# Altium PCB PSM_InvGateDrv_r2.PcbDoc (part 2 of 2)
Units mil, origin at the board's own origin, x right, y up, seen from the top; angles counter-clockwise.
Board outline 5413.39 x 2000 mil, 2 copper layers (Top Layer, Bottom Layer), stack 62 mil thick; 132 components, 58 nets, 317 pads, 172 vias.
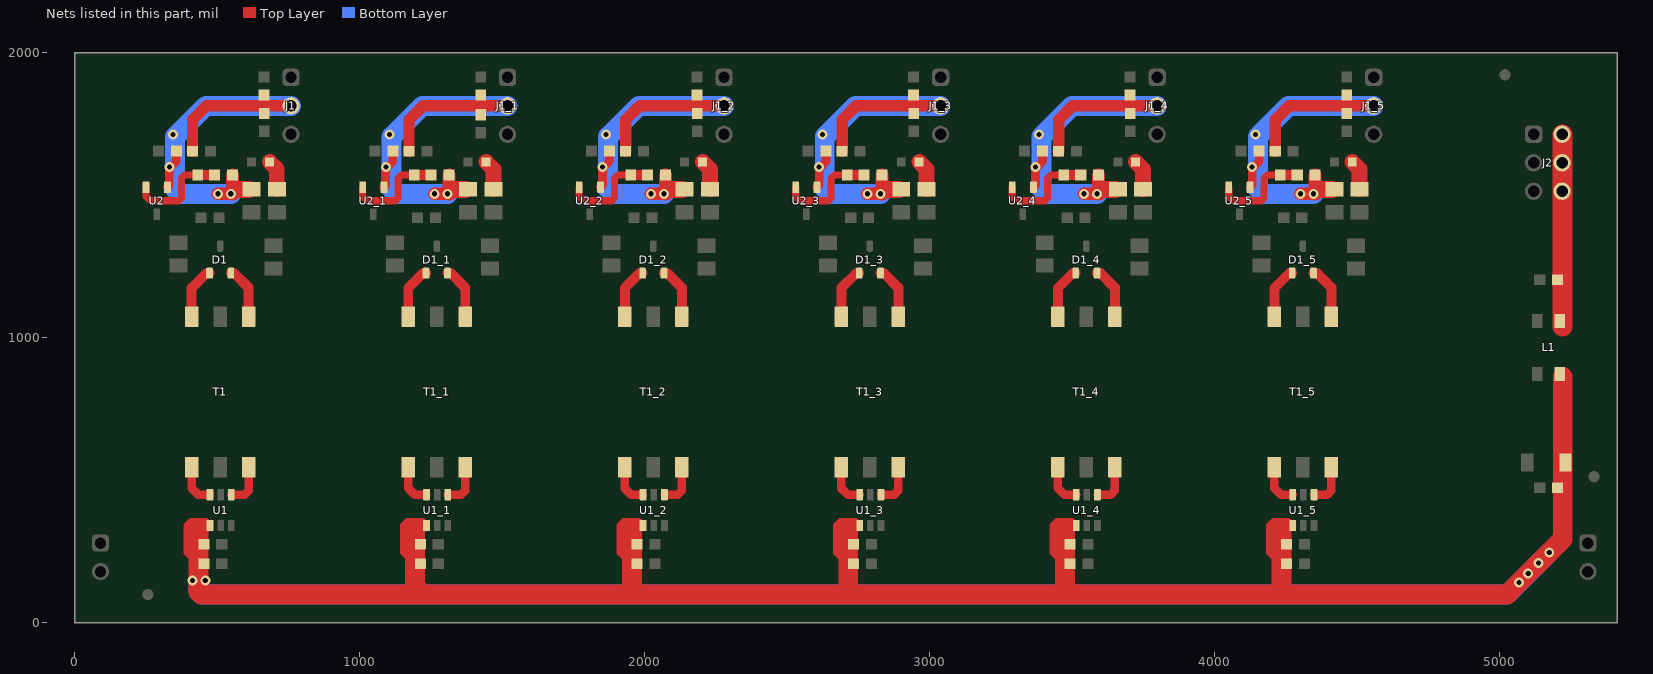
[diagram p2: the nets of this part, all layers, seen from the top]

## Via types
v1: diameter 35, hole 18, Top Layer to Bottom Layer, 172 vias

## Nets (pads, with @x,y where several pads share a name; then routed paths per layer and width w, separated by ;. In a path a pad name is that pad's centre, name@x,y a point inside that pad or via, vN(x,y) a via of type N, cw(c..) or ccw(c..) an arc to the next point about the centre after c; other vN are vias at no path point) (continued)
AGND: C2.2 C2_1.2 C2_2.2 C2_3.2 C2_4.2 C2_5.2 C3.2 C3_1.2 C3_2.2 C3_3.2 C3_4.2 C3_5.2 C8.2 C12.2 L1.2 U1.4 U1_1.4 U1_2.4 U1_3.4 U1_4.4 U1_5.4 | length 13894.7
  Top Layer w25: 423.35,217.32 393.83,246.85 393.83,340.83 408.12,355.12 460.24,355.12 U1.4@474.54,340.83 452.88,319.17 C3.2@452.88,275.42 C2.2@452.88,206.52 ; 1183.35,217.32 1153.83,246.85 1153.83,340.83 1168.12,355.12 1220.24,355.12 U1_1.4@1234.54,340.83 1212.88,319.17 C3_1.2@1212.88,275.42 C2_1.2@1212.88,206.52 ; 1943.35,217.32 1913.83,246.85 1913.83,340.83 1928.12,355.12 1980.24,355.12 U1_2.4@1994.54,340.83 1972.88,319.17 C3_2.2@1972.88,275.42 C2_2.2@1972.88,206.52 ; 2703.35,217.32 2673.83,246.85 2673.83,340.83 2688.12,355.12 2740.24,355.12 U1_3.4@2754.54,340.83 2732.88,319.17 C3_3.2@2732.88,275.42 C2_3.2@2732.88,206.52 ; 3463.35,217.32 3433.83,246.85 3433.83,340.83 3448.12,355.12 3500.24,355.12 U1_4.4@3514.54,340.83 3492.88,319.17 C3_4.2@3492.88,275.42 C2_4.2@3492.88,206.52 ; 4223.35,217.32 4193.83,246.85 4193.83,340.83 4208.12,355.12 4260.24,355.12 U1_5.4@4274.54,340.83 4252.88,319.17 C3_5.2@4252.88,275.42 C2_5.2@4252.88,206.52
  Top Layer w70: 434.67,329.19 434.67,206.52 434.67,108.71 444.98,98.41 1222.99,98.41 ; C3_1.2@1193.63,275.42 1193.63,319.35 ; C3_1.2@1194.67,275.42 1194.67,126.73 1222.99,98.41 ; 1954.94,109.05 1954.94,329.53 ; 2714.67,329.19 2714.67,275.42 2714.67,108.71 2724.98,98.41 ; 3474.67,329.19 3474.67,275.42 3474.67,108.71 3484.98,98.41 ; 4234.67,98.41 5026.87,98.41 5222.38,293.91 5222.38,472.91 5222.38,561.5 L1.2@5222.38,862.11 ; 4234.67,329.19 4234.67,275.42 4234.67,108.71 4244.98,98.41 3484.98,98.41 ; 1222.99,98.41 2724.98,98.41 ; 2724.98,98.41 3484.98,98.41
  Bottom Layer w70: 434.67,138.27 434.67,108.71 444.49,98.9 5027.36,98.9 v1(5175,246.54)
  other v1: 5068.9,140.43 413.51,148.11 457.88,148.11 5101.18,172.72 5137.8,209.33
NetC11_2: C11.2 J2.2 J2.4 J2.6 L1.3 | length 674.5
  Top Layer w70: L1.3@5220.8,1039.51 J2.2@5220.8,1714
NetD1_1: D1.1 T1.6 | length 168.7
  Top Layer w35: T1.6@410.26,1089.84 410.26,1174.09 463.02,1226.85 D1.1@472.86,1226.85
NetD1_1_1: D1_1.1 T1_1.6 | length 168.7
  Top Layer w35: T1_1.6@1170.26,1089.84 1170.26,1174.09 1223.02,1226.85 D1_1.1@1232.86,1226.85
NetD1_1_2: D1_1.2 T1_1.4 | length 169.7
  Top Layer w35: D1_1.2@1307.67,1226.85 1319.18,1226.85 1370.26,1175.77 T1_1.4@1370.26,1089.84
NetD1_2: D1.2 T1.4 | length 169.7
  Top Layer w35: D1.2@547.67,1226.85 559.18,1226.85 610.26,1175.77 T1.4@610.26,1089.84
NetD1_2_1: D1_2.1 T1_2.6 | length 168.7
  Top Layer w35: T1_2.6@1930.26,1089.84 1930.26,1174.09 1983.02,1226.85 D1_2.1@1992.86,1226.85
NetD1_2_2: D1_2.2 T1_2.4 | length 169.7
  Top Layer w35: D1_2.2@2067.67,1226.85 2079.18,1226.85 2130.26,1175.77 T1_2.4@2130.26,1089.84
NetD1_3_1: D1_3.1 T1_3.6 | length 168.7
  Top Layer w35: T1_3.6@2690.26,1089.84 2690.26,1174.09 2743.02,1226.85 D1_3.1@2752.86,1226.85
NetD1_3_2: D1_3.2 T1_3.4 | length 169.7
  Top Layer w35: D1_3.2@2827.67,1226.85 2839.18,1226.85 2890.26,1175.77 T1_3.4@2890.26,1089.84
NetD1_4_1: D1_4.1 T1_4.6 | length 168.7
  Top Layer w35: T1_4.6@3450.26,1089.84 3450.26,1174.09 3503.02,1226.85 D1_4.1@3512.86,1226.85
NetD1_4_2: D1_4.2 T1_4.4 | length 169.7
  Top Layer w35: D1_4.2@3587.67,1226.85 3599.18,1226.85 3650.26,1175.77 T1_4.4@3650.26,1089.84
NetD1_5_1: D1_5.1 T1_5.6 | length 168.7
  Top Layer w35: T1_5.6@4210.26,1089.84 4210.26,1174.09 4263.02,1226.85 D1_5.1@4272.86,1226.85
NetD1_5_2: D1_5.2 T1_5.4 | length 169.7
  Top Layer w35: D1_5.2@4347.67,1226.85 4359.18,1226.85 4410.26,1175.77 T1_5.4@4410.26,1089.84
NetD2_1_2: D2_1.2 R1_1.1 | length 107
  Top Layer w55: D2_1.2@1443.59,1617.15 1469.18,1591.56 R1_1.1@1469.18,1520.79
NetD2_2: D2.2 R1.1 | length 107
  Top Layer w55: D2.2@683.59,1617.15 709.18,1591.56 R1.1@709.18,1520.79
NetD2_2_2: D2_2.2 R1_2.1 | length 107
  Top Layer w55: D2_2.2@2203.59,1617.15 2229.18,1591.56 R1_2.1@2229.18,1520.79
NetD2_3_2: D2_3.2 R1_3.1 | length 107
  Top Layer w55: D2_3.2@2963.59,1617.15 2989.18,1591.56 R1_3.1@2989.18,1520.79
NetD2_4_2: D2_4.2 R1_4.1 | length 107
  Top Layer w55: D2_4.2@3723.59,1617.15 3749.18,1591.56 R1_4.1@3749.18,1520.79
NetD2_5_2: D2_5.2 R1_5.1 | length 107
  Top Layer w55: D2_5.2@4483.59,1617.15 4509.18,1591.56 R1_5.1@4509.18,1520.79
NetR3_1: R3.1 R4.2 U2.2 | length 350.1
  Top Layer w25: U2.2@250.13,1528.03 250.13,1496.54 265.87,1480.79 364.3,1480.79 374.14,1490.63 374.14,1559.53 385.95,1571.34 R4.2@431.33,1571.34
  Top Layer w35: R4.2@431.33,1571.34 R3.1@484.38,1571.34
NetR3_1_1: R3_1.1 R4_1.2 U2_1.2 | length 350.1
  Top Layer w25: U2_1.2@1010.13,1528.03 1010.13,1496.54 1025.87,1480.79 1124.3,1480.79 1134.14,1490.63 1134.14,1559.53 1145.95,1571.34 R4_1.2@1191.33,1571.34
  Top Layer w35: R4_1.2@1191.33,1571.34 R3_1.1@1244.38,1571.34
NetR3_2_1: R3_2.1 R4_2.2 U2_2.2 | length 350.1
  Top Layer w25: U2_2.2@1770.13,1528.03 1770.13,1496.54 1785.87,1480.79 1884.3,1480.79 1894.14,1490.63 1894.14,1559.53 1905.95,1571.34 R4_2.2@1951.33,1571.34
  Top Layer w35: R4_2.2@1951.33,1571.34 R3_2.1@2004.38,1571.34
NetR3_3_1: R3_3.1 R4_3.2 U2_3.2 | length 350.1
  Top Layer w25: U2_3.2@2530.13,1528.03 2530.13,1496.54 2545.87,1480.79 2644.3,1480.79 2654.14,1490.63 2654.14,1559.53 2665.95,1571.34 R4_3.2@2711.33,1571.34
  Top Layer w35: R4_3.2@2711.33,1571.34 R3_3.1@2764.38,1571.34
NetR3_4_1: R3_4.1 R4_4.2 U2_4.2 | length 350.1
  Top Layer w25: U2_4.2@3290.13,1528.03 3290.13,1496.54 3305.87,1480.79 3404.3,1480.79 3414.14,1490.63 3414.14,1559.53 3425.95,1571.34 R4_4.2@3471.33,1571.34
  Top Layer w35: R4_4.2@3471.33,1571.34 R3_4.1@3524.38,1571.34
NetR3_5_1: R3_5.1 R4_5.2 U2_5.2 | length 350.1
  Top Layer w25: U2_5.2@4050.13,1528.03 4050.13,1496.54 4065.87,1480.79 4164.3,1480.79 4174.14,1490.63 4174.14,1559.53 4185.95,1571.34 R4_5.2@4231.33,1571.34
  Top Layer w35: R4_5.2@4231.33,1571.34 R3_5.1@4284.38,1571.34
NetT1_1: T1.1 U1.3 | length 131.3
  Top Layer w30: T1.1@410.26,530 410.26,472.03 433.2,449.09 U1.3@474.06,449.09
NetT1_1_1: T1_1.1 U1_1.3 | length 131.3
  Top Layer w30: T1_1.1@1170.26,530 1170.26,472.03 1193.2,449.09 U1_1.3@1234.06,449.09
NetT1_1_3: T1_1.3 U1_1.1 | length 132.8
  Top Layer w30: U1_1.1@1309.81,449.09 1355.6,449.09 1370.26,463.76 T1_1.3@1370.26,530
NetT1_2_1: T1_2.1 U1_2.3 | length 131.3
  Top Layer w30: T1_2.1@1930.26,530 1930.26,472.03 1953.2,449.09 U1_2.3@1994.06,449.09
NetT1_2_3: T1_2.3 U1_2.1 | length 132.8
  Top Layer w30: U1_2.1@2069.81,449.09 2115.6,449.09 2130.26,463.76 T1_2.3@2130.26,530
NetT1_3: T1.3 U1.1 | length 132.8
  Top Layer w30: U1.1@549.81,449.09 595.6,449.09 610.26,463.76 T1.3@610.26,530
NetT1_3_1: T1_3.1 U1_3.3 | length 131.3
  Top Layer w30: T1_3.1@2690.26,530 2690.26,472.03 2713.2,449.09 U1_3.3@2754.06,449.09
NetT1_3_3: T1_3.3 U1_3.1 | length 132.8
  Top Layer w30: U1_3.1@2829.81,449.09 2875.6,449.09 2890.26,463.76 T1_3.3@2890.26,530
NetT1_4_1: T1_4.1 U1_4.3 | length 131.3
  Top Layer w30: T1_4.1@3450.26,530 3450.26,472.03 3473.2,449.09 U1_4.3@3514.06,449.09
NetT1_4_3: T1_4.3 U1_4.1 | length 132.8
  Top Layer w30: U1_4.1@3589.81,449.09 3635.6,449.09 3650.26,463.76 T1_4.3@3650.26,530
NetT1_5_1: T1_5.1 U1_5.3 | length 131.3
  Top Layer w30: T1_5.1@4210.26,530 4210.26,472.03 4233.2,449.09 U1_5.3@4274.06,449.09
NetT1_5_3: T1_5.3 U1_5.1 | length 132.8
  Top Layer w30: U1_5.1@4349.81,449.09 4395.6,449.09 4410.26,463.76 T1_5.3@4410.26,530
S_1: C1.2 C7.1 C9.2 C10.1 J1.2 R2.1 R3.2 U2.1 | length 1632.6
  Top Layer w30: U2.1@324.93,1528.03 332.02,1535.12 v1(332.02,1598.72) 336.02,1598.72 356.43,1619.12 C9.2@356.43,1655.54
  Top Layer w40: C10.1@412.04,1655.54 C10.1@413.02,1654.55 413.02,1725.87 413.02,1764.44 462.58,1814 J1.2@758.63,1814
  Top Layer w45: v1(502.09,1505.2) v1(547.37,1505.2) 553.28,1511.1 R3.2@553.28,1571.34
  Top Layer w60: v1@553.28,1511.1 562.96,1520.79 R2.1@610.76,1520.79
  Bottom Layer w70: v1(547.37,1505.2) v1(502.09,1505.2) 369.42,1505.2 352.09,1522.52 352.09,1705.59 460.5,1814 J1.2@758.63,1814
  other v1: 344.49,1713.87
S_2: C1_1.2 C7_1.1 C9_1.2 C10_1.1 J1_1.2 R2_1.1 R3_1.2 U2_1.1 | length 1632.6
  Top Layer w30: U2_1.1@1084.93,1528.03 1092.02,1535.12 v1(1092.02,1598.72) 1096.02,1598.72 1116.43,1619.12 C9_1.2@1116.43,1655.54
  Top Layer w40: C10_1.1@1172.04,1655.54 C10_1.1@1173.02,1654.55 1173.02,1725.87 1173.02,1764.44 1222.58,1814 J1_1.2@1518.63,1814
  Top Layer w45: v1(1262.09,1505.2) v1(1307.37,1505.2) 1313.28,1511.1 R3_1.2@1313.28,1571.34
  Top Layer w60: v1@1313.28,1511.1 1322.96,1520.79 R2_1.1@1370.76,1520.79
  Bottom Layer w70: v1(1307.37,1505.2) v1(1262.09,1505.2) 1129.42,1505.2 1112.09,1522.52 1112.09,1705.59 1220.5,1814 J1_1.2@1518.63,1814
  other v1: 1104.49,1713.87
S_3: C1_2.2 C7_2.1 C9_2.2 C10_2.1 J1_2.2 R2_2.1 R3_2.2 U2_2.1 | length 1632.6
  Top Layer w30: U2_2.1@1844.93,1528.03 1852.02,1535.12 v1(1852.02,1598.72) 1856.02,1598.72 1876.43,1619.12 C9_2.2@1876.43,1655.54
  Top Layer w40: C10_2.1@1932.04,1655.54 C10_2.1@1933.02,1654.55 1933.02,1725.87 1933.02,1764.44 1982.58,1814 J1_2.2@2278.63,1814
  Top Layer w45: v1(2022.09,1505.2) v1(2067.37,1505.2) 2073.28,1511.1 R3_2.2@2073.28,1571.34
  Top Layer w60: v1@2073.28,1511.1 2082.96,1520.79 R2_2.1@2130.76,1520.79
  Bottom Layer w70: v1(2067.37,1505.2) v1(2022.09,1505.2) 1889.42,1505.2 1872.09,1522.52 1872.09,1705.59 1980.5,1814 J1_2.2@2278.63,1814
  other v1: 1864.49,1713.87
S_4: C1_3.2 C7_3.1 C9_3.2 C10_3.1 J1_3.2 R2_3.1 R3_3.2 U2_3.1 | length 1632.6
  Top Layer w30: U2_3.1@2604.93,1528.03 2612.02,1535.12 v1(2612.02,1598.72) 2616.02,1598.72 2636.43,1619.12 C9_3.2@2636.43,1655.54
  Top Layer w40: C10_3.1@2692.04,1655.54 C10_3.1@2693.02,1654.55 2693.02,1725.87 2693.02,1764.44 2742.58,1814 J1_3.2@3038.63,1814
  Top Layer w45: v1(2782.09,1505.2) v1(2827.37,1505.2) 2833.28,1511.1 R3_3.2@2833.28,1571.34
  Top Layer w60: v1@2833.28,1511.1 2842.96,1520.79 R2_3.1@2890.76,1520.79
  Bottom Layer w70: v1(2827.37,1505.2) v1(2782.09,1505.2) 2649.42,1505.2 2632.09,1522.52 2632.09,1705.59 2740.5,1814 J1_3.2@3038.63,1814
  other v1: 2624.49,1713.87
S_5: C1_4.2 C7_4.1 C9_4.2 C10_4.1 J1_4.2 R2_4.1 R3_4.2 U2_4.1 | length 1632.6
  Top Layer w30: U2_4.1@3364.93,1528.03 3372.02,1535.12 v1(3372.02,1598.72) 3376.02,1598.72 3396.43,1619.12 C9_4.2@3396.43,1655.54
  Top Layer w40: C10_4.1@3452.04,1655.54 C10_4.1@3453.02,1654.55 3453.02,1725.87 3453.02,1764.44 3502.58,1814 J1_4.2@3798.63,1814
  Top Layer w45: v1(3542.09,1505.2) v1(3587.37,1505.2) 3593.28,1511.1 R3_4.2@3593.28,1571.34
  Top Layer w60: v1@3593.28,1511.1 3602.96,1520.79 R2_4.1@3650.76,1520.79
  Bottom Layer w70: v1(3587.37,1505.2) v1(3542.09,1505.2) 3409.42,1505.2 3392.09,1522.52 3392.09,1705.59 3500.5,1814 J1_4.2@3798.63,1814
  other v1: 3384.49,1713.87
S_6: C1_5.2 C7_5.1 C9_5.2 C10_5.1 J1_5.2 R2_5.1 R3_5.2 U2_5.1 | length 1632.6
  Top Layer w30: U2_5.1@4124.93,1528.03 4132.02,1535.12 v1(4132.02,1598.72) 4136.02,1598.72 4156.43,1619.12 C9_5.2@4156.43,1655.54
  Top Layer w40: C10_5.1@4212.04,1655.54 C10_5.1@4213.02,1654.55 4213.02,1725.87 4213.02,1764.44 4262.58,1814 J1_5.2@4558.63,1814
  Top Layer w45: v1(4302.09,1505.2) v1(4347.37,1505.2) 4353.28,1511.1 R3_5.2@4353.28,1571.34
  Top Layer w60: v1@4353.28,1511.1 4362.96,1520.79 R2_5.1@4410.76,1520.79
  Bottom Layer w70: v1(4347.37,1505.2) v1(4302.09,1505.2) 4169.42,1505.2 4152.09,1522.52 4152.09,1705.59 4260.5,1814 J1_5.2@4558.63,1814
  other v1: 4144.49,1713.87
pads on no net: FID1.1 FID2.1 FID3.1 J3.1 J3.2 J4.1 J4.2 U1.6 U1_1.6 U1_2.6 U1_3.6 U1_4.6 U1_5.6

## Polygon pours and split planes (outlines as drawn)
-4V_2 on Top Layer "TOP_LAYER_-4V_2_P030" (solid, pour order 30): 1528,1745.75 1547.53,1726.22 1547.53,1657.17 1525.23,1634.87 1239.91,1634.87 1222.37,1652.41 1222.37,1704.12 1264.5,1745.75
S_2 on Top Layer "TOP_LAYER_S_2_P028" (solid, pour order 28): 1539.39,1765.72 1568.63,1794.96 1568.63,1850.22 1547.53,1871.32 1121.13,1871.32 1094.77,1844.96 1094.77,1615.43 1112.09,1598.11 1183.23,1598.11 1202.91,1617.8 1202.91,1742.77 1225.57,1765.43 1537.28,1765.43 1537.56,1765.72
+15V_2 on Top Layer "TOP_LAYER_+15V_2_P026" (solid, pour order 26): 986.38,1598.11 1057.05,1598.11 1074.96,1616.02 1074.96,1851.64 1106.87,1883.54 1548.94,1883.54 1568.63,1903.23 1568.63,1953.37 1558,1964 1037.31,1964 976.54,1903.23 976.54,1607.95
5Vs on Top Layer "TOP_LAYER_5VS_P098" (solid, pour order 98): 511.81,295.51 513.44,297.14 610.24,297.14 629.92,277.46 629.92,183.63 615.48,169.19 520.6,169.19 501.97,187.82 501.97,282.45 516.66,297.14
5Vs on Top Layer "TOP_LAYER_5VS_P096" (solid, pour order 96): 1270.63,295.51 1272.26,297.14 1369.06,297.14 1388.74,277.46 1388.74,183.63 1374.3,169.19 1279.42,169.19 1260.79,187.82 1260.79,282.45 1275.48,297.14
5Vs on Top Layer "TOP_LAYER_5VS_P094" (solid, pour order 94): 2029.45,295.51 2031.08,297.14 2127.87,297.14 2147.56,277.46 2147.56,183.63 2133.12,169.19 2038.24,169.19 2019.61,187.82 2019.61,282.45 2034.3,297.14
5Vs on Top Layer "TOP_LAYER_5VS_P092" (solid, pour order 92): 2788.27,295.51 2789.9,297.14 2886.69,297.14 2906.38,277.46 2906.38,183.63 2891.94,169.19 2797.06,169.19 2778.43,187.82 2778.43,282.45 2793.12,297.14
5Vs on Top Layer "TOP_LAYER_5VS_P090" (solid, pour order 90): 3547.09,294.12 3548.72,295.75 3645.51,295.75 3665.2,276.06 3665.2,182.24 3650.76,167.8 3555.87,167.8 3537.24,186.43 3537.24,281.06 3551.94,295.75
5Vs on Top Layer "TOP_LAYER_5VS_P086" (solid, pour order 86): 4335.43,295.75 4852.36,295.75 5048.17,491.56 5167.32,490.8 5167.32,374.49 4960.63,167.8 4344.76,167.8 4306.03,206.52 4306.03,266.35
-4V_6 on Top Layer "TOP_LAYER_-4V_6_P080" (solid, pour order 80): 4568,1745.75 4587.53,1726.22 4587.53,1657.17 4565.23,1634.87 4279.91,1634.87 4262.37,1652.41 4262.37,1704.12 4304.5,1745.75
S_6 on Top Layer "Top Layer-S_1" (solid, pour order 78): 4579.39,1765.72 4608.63,1794.96 4608.63,1850.22 4587.53,1871.32 4161.13,1871.32 4134.77,1844.96 4134.77,1615.43 4152.09,1598.11 4223.23,1598.11 4242.91,1617.8 4242.91,1742.77 4265.57,1765.43 4577.28,1765.43 4577.56,1765.72
+15V_6 on Top Layer "TOP_LAYER_+15V_6_P076" (solid, pour order 76): 4026.38,1598.11 4097.05,1598.11 4114.96,1616.02 4114.96,1851.64 4146.87,1883.54 4588.94,1883.54 4608.63,1903.23 4608.63,1953.37 4598,1964 4077.31,1964 4016.54,1903.23 4016.54,1607.95
-4V_5 on Top Layer "TOP_LAYER_-4V_5_P070" (solid, pour order 70): 3808,1745.75 3827.53,1726.22 3827.53,1657.17 3805.23,1634.87 3519.91,1634.87 3502.37,1652.41 3502.37,1704.12 3544.5,1745.75
S_5 on Top Layer "Top Layer-S_1" (solid, pour order 68): 3819.39,1765.72 3848.63,1794.96 3848.63,1850.22 3827.53,1871.32 3401.13,1871.32 3374.77,1844.96 3374.77,1615.43 3392.09,1598.11 3463.23,1598.11 3482.91,1617.8 3482.91,1742.77 3505.57,1765.43 3817.28,1765.43 3817.56,1765.72
+15V_5 on Top Layer "TOP_LAYER_+15V_5_P066" (solid, pour order 66): 3266.38,1598.11 3337.05,1598.11 3354.96,1616.02 3354.96,1851.64 3386.87,1883.54 3828.94,1883.54 3848.63,1903.23 3848.63,1953.37 3838,1964 3317.31,1964 3256.54,1903.23 3256.54,1607.95
-4V_4 on Top Layer "TOP_LAYER_-4V_4_P060" (solid, pour order 60): 3048,1745.75 3067.53,1726.22 3067.53,1657.17 3045.23,1634.87 2759.91,1634.87 2742.37,1652.41 2742.37,1704.12 2784.5,1745.75
S_4 on Top Layer "Top Layer-S_1" (solid, pour order 58): 3059.39,1765.72 3088.63,1794.96 3088.63,1850.22 3067.53,1871.32 2641.13,1871.32 2614.77,1844.96 2614.77,1615.43 2632.09,1598.11 2703.23,1598.11 2722.91,1617.8 2722.91,1742.77 2745.57,1765.43 3057.28,1765.43 3057.56,1765.72
+15V_4 on Top Layer "TOP_LAYER_+15V_4_P056" (solid, pour order 56): 2506.38,1598.11 2577.05,1598.11 2594.96,1616.02 2594.96,1851.64 2626.87,1883.54 3068.94,1883.54 3088.63,1903.23 3088.63,1953.37 3078,1964 2557.31,1964 2496.54,1903.23 2496.54,1607.95
-4V_3 on Top Layer "TOP_LAYER_-4V_3_P050" (solid, pour order 50): 2288,1745.75 2307.53,1726.22 2307.53,1657.17 2285.23,1634.87 1999.91,1634.87 1982.37,1652.41 1982.37,1704.12 2024.5,1745.75
S_3 on Top Layer "Top Layer-S_3" (solid, pour order 48): 2299.39,1765.72 2328.63,1794.96 2328.63,1850.22 2307.53,1871.32 1881.13,1871.32 1854.77,1844.96 1854.77,1615.43 1872.09,1598.11 1943.23,1598.11 1962.91,1617.8 1962.91,1742.77 1985.57,1765.43 2297.28,1765.43 2297.56,1765.72
+15V_3 on Top Layer "TOP_LAYER_+15V_3_P046" (solid, pour order 46): 1746.38,1598.11 1817.05,1598.11 1834.96,1616.02 1834.96,1851.64 1866.87,1883.54 2308.94,1883.54 2328.63,1903.23 2328.63,1953.37 2318,1964 1797.31,1964 1736.54,1903.23 1736.54,1607.95
+15V_1 on Top Layer "TOP_LAYER_+15V_1_P024" (solid, pour order 24): 226.38,1598.11 297.05,1598.11 314.96,1616.02 314.96,1851.64 346.87,1883.54 788.94,1883.54 808.63,1903.23 808.63,1953.37 798,1964 277.31,1964 216.54,1903.23 216.54,1607.95
S_1 on Top Layer "Top Layer-S_1" (solid, pour order 20): 779.39,1765.72 808.63,1794.96 808.63,1850.22 787.53,1871.32 361.13,1871.32 334.77,1844.96 334.77,1615.43 352.09,1598.11 423.23,1598.11 442.91,1617.8 442.91,1742.77 465.57,1765.43 777.28,1765.43 777.56,1765.72
-4V_1 on Top Layer "TOP_LAYER_-4V_1_P000" (solid, pour order 0): 768,1745.75 787.53,1726.22 787.53,1657.17 765.23,1634.87 479.91,1634.87 462.37,1652.41 462.37,1704.12 504.5,1745.75
-4V_2 on Bottom Layer "BOTTOM_LAYER_-4V_2_P032" (solid, pour order 32): 1526.85,1746.88 1546.38,1727.35 1546.38,1665.98 1516.39,1636 1238.76,1636 1221.22,1653.54 1221.22,1705.25 1263.35,1746.88
5Vs on Bottom Layer "BOTTOM_LAYER_5VS_P088" (solid, pour order 88): 4413.52,325.28 4448.82,298.8 4448.82,187.24 4422.89,167.8 586.84,167.79 561.02,193.61 561.02,285.91 600.39,325.28
-4V_6 on Bottom Layer "Bottom Layer--4V_1" (solid, pour order 84): 4075.72,1333.15 4213.51,1195.35 4410.36,1195.35 4479.26,1264.25 4587.53,1264.25 4617.06,1234.72 4617.06,1087.09 4597.37,1067.4 4036.35,1067.4 4016.66,1087.09 4016.66,1313.46 4036.35,1333.15
-4V_6 on Bottom Layer "BOTTOM_LAYER_-4V_6_P082" (solid, pour order 82): 4566.85,1746.88 4586.38,1727.35 4586.38,1665.98 4556.39,1636 4278.76,1636 4261.22,1653.54 4261.22,1705.25 4303.35,1746.88
-4V_5 on Bottom Layer "Bottom Layer--4V_1" (solid, pour order 74): 3315.72,1333.15 3453.51,1195.35 3650.36,1195.35 3719.26,1264.25 3827.53,1264.25 3857.06,1234.72 3857.06,1087.09 3837.37,1067.4 3276.35,1067.4 3256.66,1087.09 3256.66,1313.46 3276.35,1333.15
-4V_5 on Bottom Layer "BOTTOM_LAYER_-4V_5_P072" (solid, pour order 72): 3806.85,1746.88 3826.38,1727.35 3826.38,1665.98 3796.39,1636 3518.76,1636 3501.22,1653.54 3501.22,1705.25 3543.35,1746.88
-4V_4 on Bottom Layer "Bottom Layer--4V_1" (solid, pour order 64): 2555.72,1333.15 2693.51,1195.35 2890.36,1195.35 2959.26,1264.25 3067.53,1264.25 3097.06,1234.72 3097.06,1087.09 3077.37,1067.4 2516.35,1067.4 2496.66,1087.09 2496.66,1313.46 2516.35,1333.15
-4V_4 on Bottom Layer "BOTTOM_LAYER_-4V_4_P062" (solid, pour order 62): 3046.85,1746.88 3066.38,1727.35 3066.38,1665.98 3036.39,1636 2758.76,1636 2741.22,1653.54 2741.22,1705.25 2783.35,1746.88
-4V_3 on Bottom Layer "Bottom Layer--4V_1" (solid, pour order 54): 1795.72,1333.15 1933.51,1195.35 2130.36,1195.35 2199.26,1264.25 2307.53,1264.25 2337.06,1234.72 2337.06,1087.09 2317.37,1067.4 1756.35,1067.4 1736.66,1087.09 1736.66,1313.46 1756.35,1333.15
-4V_3 on Bottom Layer "BOTTOM_LAYER_-4V_3_P052" (solid, pour order 52): 2286.85,1746.88 2306.38,1727.35 2306.38,1665.98 2276.39,1636 1998.76,1636 1981.22,1653.54 1981.22,1705.25 2023.35,1746.88
-4V_2 on Bottom Layer "Bottom Layer--4V_1" (solid, pour order 34): 1035.72,1333.15 1173.51,1195.35 1370.36,1195.35 1439.26,1264.25 1547.53,1264.25 1577.06,1234.72 1577.06,1087.09 1557.37,1067.4 996.35,1067.4 976.66,1087.09 976.66,1313.46 996.35,1333.15
-4V_1 on Bottom Layer "BOTTOM_LAYER_-4V_1_P022" (solid, pour order 22): 766.85,1746.88 786.38,1727.35 786.38,1665.98 756.39,1636 478.76,1636 461.22,1653.54 461.22,1705.25 503.35,1746.88
-4V_1 on Bottom Layer "Bottom Layer--4V_1" (solid, pour order 6): 275.72,1333.15 413.51,1195.35 610.36,1195.35 679.26,1264.25 787.53,1264.25 817.06,1234.72 817.06,1087.09 797.37,1067.4 236.35,1067.4 216.66,1087.09 216.66,1313.46 236.35,1333.15

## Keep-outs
Keep-Out Layer:
  text ".Layer_Name" at 577,-850.08 h60

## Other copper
Top Layer:
  text ".Layer_Name" at 577,-850.08 h60
Bottom Layer:
  text ".Layer_Name" at 577,-850.08 h60

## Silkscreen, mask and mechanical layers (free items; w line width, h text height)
Top Overlay:
  lines w10: 215.87,1745.5 215.87,1963.34 ; 216.66,305.91 216.66,561.81 364.3,561.81 ; 216.66,1598.11 216.66,1057.09 364.3,1057.09 ; 639.89,561.81 807.21,561.81 807.21,302.62 ; 649.73,1057.09 807.21,1057.09 807.21,1640.54 ; 975.87,1745.5 975.87,1963.34 ; 976.66,305.91 976.66,561.81 1124.3,561.81 ; 976.66,1598.11 976.66,1057.09 1124.3,1057.09 ; 1399.89,561.81 1567.21,561.81 1567.21,302.62 ; 1409.73,1057.09 1567.21,1057.09 1567.21,1640.54 ; 1735.87,1745.5 1735.87,1963.34 ; 1736.66,305.91 1736.66,561.81 1884.3,561.81 ; 1736.66,1598.11 1736.66,1057.09 1884.3,1057.09 ; 2159.89,561.81 2327.21,561.81 2327.21,302.62 ; 2169.73,1057.09 2327.21,1057.09 2327.21,1640.54 ; 2495.87,1745.5 2495.87,1963.34 ; 2496.66,305.91 2496.66,561.81 2644.3,561.81 ; 2496.66,1598.11 2496.66,1057.09 2644.3,1057.09 ; 2919.89,561.81 3087.21,561.81 3087.21,302.62 ; 2929.73,1057.09 3087.21,1057.09 3087.21,1640.54 ; 3255.87,1745.5 3255.87,1963.34 ; 3256.66,305.91 3256.66,561.81 3404.3,561.81 ; 3256.66,1598.11 3256.66,1057.09 3404.3,1057.09 ; 3679.89,561.81 3847.21,561.81 3847.21,302.62 ; 3689.73,1057.09 3847.21,1057.09 3847.21,1640.54 ; 4015.87,1745.5 4015.87,1963.34 ; 4016.66,305.91 4016.66,561.81 4164.3,561.81 ; 4016.66,1598.11 4016.66,1057.09 4164.3,1057.09 ; 4439.89,561.81 4607.21,561.81 4607.21,302.62 ; 4449.73,1057.09 4607.21,1057.09 4607.21,1640.54
  lines w20: 206.69,778.03 4921.26,773.87 4921.26,1968.98
  text "+5V GND" at 5039.37,1815.97 h40
  text "VEE GND VCC" at 4675.2,1607.95 h35 r90
  text "VEE GND VCC" at 1633.86,1600.46 h35 r90
  text "VEE GND VCC" at 2391.73,1600.46 h35 r90
  text "VEE GND VCC" at 3149.61,1600.46 h35 r90
  text "VEE GND VCC" at 3917.32,1600.46 h35 r90
  text "VEE GND VCC" at 866.14,1598.11 h35 r90
  text "High Voltage" at 4833.44,1175.2 h110 r90
  text "HIGH VOLTAGE" at 2215.24,805.5 h80
  text "LOW VOLTAGE" at 2217.3,696 h80
  text "Power Supply - Inverter Gate Driver" at 98.43,407.66 h90 r90
  text "'.PRJ_Number'.PCB_Rev" at 177.17,407.66 h70 r90
  text "CL" at 423.35,69 h80
  text "CH" at 1175,68 h80
  text "BL" at 1936,64 h80
  text "BH" at 2697.23,61 h80
  text "AL" at 3456,59 h80
  text "AH" at 4217,59 h80
  text ".Layer_Name" at 577,-850.08 h60
Bottom Overlay:
  lines w20: 39.37,710.71 4921.26,710.71 4921.26,1968.98
  text "High Voltage" at 2574.11,1037.09 h110 r180
  text "HIGH VOLTAGE" at 635.96,791.4 h80 r180
  text "HIGH VOLTAGE" at 4045.91,790.45 h80 r180
  text "LOW VOLTAGE" at 642,679 h80 r180
  text "LOW VOLTAGE" at 4051.95,678.05 h80 r180
  text "CL" at 429.35,249 h72.83 r180
  text "CH" at 1181,248 h72.83 r180
  text "BL" at 1942,244 h72.83 r180
  text "BH" at 2703.23,241 h72.83 r180
  text "AL" at 3462,239 h72.83 r180
  text "AH" at 4223,239 h72.83 r180
  text ".Layer_Name" at 577,-850.08 h60
Top Paste:
  text ".Layer_Name" at 577,-850.08 h60
Bottom Paste:
  text ".Layer_Name" at 577,-850.08 h60
Top Solder:
  text ".Layer_Name" at 577,-850.08 h60
  text ".Layer_Name" at 577,-850.08 h60
Bottom Solder:
  text ".Layer_Name" at 577,-850.08 h60
Drill Guide:
  text ".Layer_Name" at 577,-850.08 h60
M1 Board Outline:
  the board outline again, w10
  text ".Layer_Name" at 577,-850.08 h60
M2 Board Dimensions:
  rectangle: 0,-266.59 125,-141.59
  rectangle: 125,-391.59 500,-266.59
  lines w7: 0,-266.59 1000,-266.59 ; 125,-391.59 125,-141.59 ; 250,-391.59 250,-141.59 ; 500,-391.59 500,-141.59 ; 750,-391.59 750,-141.59 ; 0,-391.59 1000,-391.59 1000,-141.59 0,-141.59 0,-391.59
  text ".Layer_Name" at 577,-850.08 h60
M3 3D STEP Top:
  text ".Layer_Name" at 577,-850.08 h60
M4 3D STEP Bottom:
  text ".Layer_Name" at 577,-850.08 h60
M5 Assembly Top:
  lines w10: -292,-921.76 6308,-921.76 ; -292,-718.42 6310,-718.42 ; -292,-515.09 -292,-1125.09 3713,-1125.09 6310,-1125.09 6310,-515.09 -291.5,-515.09 -291.5,-1125.09 1284,-1125.09 ; 2173,-1125.09 2173,-515.09 ; 3440,-718.42 3440,-515.09 ; 4280,-718.42 4280,-515.09 ; 4902,-1131.59 4902,-928.76
  text "COMPONENTS MARKED 'DNP' SHOULD NOT BE POPULATED." at 1153.5,-310.09 h60
  text "ASSEMBLY VARIANT:" at 1153,-425.59 h60
  text ".VariantName" at 2189,-425.59 h60
  text "PCB VIEWED FROM TOP SIDE" at -228.5,-647.26 h60
  text "BOARD #:" at 2248,-647.26 h60
  text ".PRJ_Number" at 2793.5,-647.26 h60
  text "REV:" at 3638,-647.26 h60
  text ".PCB_Rev" at 3929.5,-647.26 h60
  text "SVN REV:" at 4476,-647.26 h60
  text ".VersionControl_RevNumber" at 4982,-647.26 h60
  text "TID #:" at 2248,-850.59 h60
  text ".TID" at 2793.5,-850.59 h60
  text "PLOT NAME =" at -228.5,-1055.93 h60
  text ".plot_File_Name" at 577,-1055.93 h60
  text "GENERATED    :" at 2250,-1055.93 h60
  text ".Print_Date" at 3119.5,-1055.93 h60
  text ".Print_Time" at 3848.5,-1055.93 h60
  text "TEXAS INSTRUMENTS" at 5113,-1055.93 h60
M6 Assembly Bottom:
  lines w10: -292.5,-718.92 6309.5,-718.92 ; -290.5,-922.26 6309.5,-922.26 ; 1115.5,-1132.09 1115.5,-929.26 ; 1737.5,-718.92 1737.5,-515.59 ; 2577.5,-718.92 2577.5,-515.59 ; 3844.5,-1125.59 3844.5,-515.59 ; 4733.5,-1125.59 6309,-1125.59 6309,-515.59 -292.5,-515.59 -292.5,-1125.59 2304.5,-1125.59 6309.5,-1125.59 6309.5,-515.59
  text "COMPONENTS MARKED 'DNP' SHOULD NOT BE POPULATED." at 6102,-309.59 h60
  text ".VariantName" at 5058,-425.59 h60
  text "ASSEMBLY VARIANT:" at 6097,-425.59 h60
  text ".VersionControl_RevNumber" at 1035.5,-647.76 h60
  text "SVN REV:" at 1541.5,-647.76 h60
  text ".PCB_Rev" at 2088,-647.76 h60
  text "REV:" at 2379.5,-647.76 h60
  text ".PRJ_Number" at 3224,-647.76 h60
  text "BOARD #:" at 3769.5,-647.76 h60
  text "PCB VIEWED FROM BOTTOM SIDE" at 6246,-647.76 h60
  text ".TID" at 3224,-851.09 h60
  text "TID #:" at 3769.5,-851.09 h60
  text "TEXAS INSTRUMENTS" at 904.5,-1056.43 h60
  text ".Print_Time" at 2169,-1056.43 h60
  text ".Print_Date" at 2898,-1056.43 h60
  text "GENERATED    :" at 3767.5,-1056.43 h60
  text ".plot_File_Name" at 5440.5,-1056.43 h60
  text "PLOT NAME =" at 6246,-1056.43 h60
M9 Title Sheet:
  drawing of 57 lines, arcs and shapes, not listed
  text "1" at 739.84,8044.91 h70
  text "2" at 3235.5,8044.91 h70
  text "3" at 5724.84,8044.91 h70
  text "4" at 8231.51,8044.91 h70
  text "5" at 10730.5,8044.91 h70
  text "6" at 13235.5,8044.91 h70
  text "A" at -416.5,6901.91 h70
  text "A" at 14383.5,6901.91 h70
  text "B" at -416.5,4521.91 h70
  text "B" at 14383.5,4521.91 h70
  text "C" at -416.5,2146.91 h70
  text "C" at 14383.5,2146.91 h70
  text "PROJECT TITLE:" at 11343.5,285.91 h45
  text ".PRJ_Title" at 11393.5,152.58 h70
  text "DESIGNED FOR:" at 11343.5,-15.09 h45
  text ".PRJ_Customer" at 11393.5,-155.09 h70
  text "D" at -416.5,-223.09 h70
  text "D" at 14383.5,-223.09 h70
  text "FILE NAME:" at 11343.5,-315.09 h45
  text ".PCB_File_Name_No_Path" at 11393.5,-435.09 h70
  text "Texas Instruments (TI) and/or its licensors do not warrant the accuracy or completeness of this specification" at 6374,-596.93 h45
  text "ENGINEER:" at 11343.5,-605.09 h45
  text "LAYOUT BY:" at 12848.5,-605.09 h45
  text "or any information contained therein. TI and/or its licensors do not warrant that this design will meet" at 6329.01,-709.59 h45
  text ".PRJ_Engineer" at 11393.5,-760.08 h70
  text ".PCB_Layout" at 12899,-760.08 h70
  text "the specifications, will be suitable for your application or fit for any particular purpose, or will operate in" at 6329.01,-822.26 h45
  text ".Layer_Name" at 577,-850.08 h60
  text "ALTIUM DESIGNER VERSION:" at 12848.5,-915.09 h45
  text "an implementation. TI and/or its licensors do not warrant that the design is production worthy. You should" at 6329.01,-934.93 h45
  text "completely validate and test your design implementation to confirm the system functionality for your application." at 6374,-1047.59 h45
  text ".print_Scale" at 11393.5,-1048.42 h70
  text ".Application_BuildNumber" at 12899,-1048.42 h70
  text "1" at 739.84,-1255.09 h70
  text "2" at 3235.5,-1255.09 h70
  text "3" at 5724.84,-1255.09 h70
  text "4" at 8231.51,-1255.09 h70
  text "5" at 10730.5,-1255.09 h70
  text "6" at 13235.5,-1255.09 h70
M10 Fab Notes:
  drawing of 189 lines, arcs and shapes, not listed
  text "DESIGN INFORMATION" at 12382.02,6364.58 h60
  text "MIN. TRACK WIDTH:" at 11737.46,6232.46 h60
  text "8" at 12833.7,6232.46 h60
  text "MIL" at 12988.46,6232.46 h60
  text "MIN. CLEARANCE:" at 11737.46,6108.33 h60
  text "0.2" at 12773.7,6108.33 h60
  text "mm" at 12988.46,6108.33 h60
  text "MIN. VIA PAD SIZE:" at 11737.46,5984.21 h60
  text "24" at 12803.71,5984.21 h60
  text "MIL" at 12988.46,5984.21 h60
  text "0.05mm (2MIL)" at 12432.46,5854.31 h60
  text "MINIMUM ANNULAR RING" at 11408.23,5846.08 h60
  text "EXTERNAL" at 13140.46,5846.08 h60
  text "PER" at 11608.23,5735.96 h60
  text "IPC-D-275 CLASS 2 LEVEL C" at 11828.23,5735.95 h60
  text "MIL, HOLES" at 13316.46,5635.48 h60
  text "+/-" at 12924,5626.89 h60
  text "+/-" at 13778,5626.89 h60
  text "REGISTRATION TOLERANCES:" at 11408.23,5625.83 h60
  text "METAL" at 12608,5625.83 h60
  text "5" at 13184.2,5625.83 h60
  text "3" at 14017.2,5625.83 h60
  text "MIL" at 14133.46,5625.83 h60
  text "HOLE SIZE TOLERANCE (UNLESS OTHERWISE SPECIFIED):" at 11408.23,5527.51 h60
  text "+/-" at 13778,5524.64 h60
  text "3" at 14017.2,5523.58 h60
  text "MIL" at 14133.46,5523.58 h60
  text "MATERIAL:" at 11333.46,5385.93 h60
  text "FR-4 High Tg" at 12319.9,5257.4 h60
  text "X" at 12175.46,5249.42 h60
  text "FR-408" at 11754.46,5244.9 h60
  text "OTHER" at 13242.46,5244.9 h60
  text "62 MIL (1.6mm) +/-10%" at 12074.56,5101.87 h60
  text "X" at 11954.46,5099.42 h60
  text "THICKNESS:" at 11408.23,5093.65 h60
  text "OTHER" at 13359.46,5093.65 h60
  text "TOLERANCE:" at 11408.23,4955.33 h60
  text "X" at 12256.46,4955.33 h60
  text "ANSI IPC-6012 TYPE 3 CLASS 2" at 12434.48,4955.33 h60
  text "OTHER +/-" at 12434.46,4811.14 h60
  text "BOW & TWIST:" at 11408.23,4665.95 h60
  text "X" at 12256.46,4665.95 h60
  text "ANSI IPC-6012 TYPE 3 CLASS 2" at 12434.48,4665.95 h60
  text "OTHER +/-" at 12434.46,4519.26 h60
  text "DRILLING:" at 11333.46,4388.64 h60
  text "NC_DRILL FILES" at 13094.46,4283.45 h60
  text "REFERENCE:" at 11408.23,4279.51 h60
  text "X" at 12065.46,4279.42 h60
  text "AS SHOWN" at 12243.46,4279.51 h60
  text "X" at 12966.46,4279.51 h60
  text "OTHER" at 13392.46,4137.26 h60
  text "PTH COPPER THICKNESS:" at 11407.91,4133.73 h60
  text "X" at 12547.14,4133.73 h60
  text "20-30 um" at 12675.14,4133.73 h60
  text "BOARD FINISH:" at 11333.46,3986.13 h60
  text "SILKSCREEN:" at 11488.68,3876.01 h60
  text "X" at 12446.46,3876.01 h60
  text "TOP" at 12563.46,3876.01 h60
  text "X" at 12956.46,3876.01 h60
  text "BOTTOM" at 13074.46,3876.01 h60
  text "SILKSCREEN COLOR:" at 11488.68,3720.82 h60
  text "X" at 12445.46,3720.82 h60
  text "WHITE" at 12563.46,3720.82 h60
  text "OTHER" at 13074.46,3720.82 h60
  text "X" at 12576.46,3577.37 h60
  text "GREEN" at 12694.46,3577.37 h60
  text "OTHER" at 13312.46,3577.37 h60
  text "SOLDER RESIST COLOR:" at 11488.68,3570.5 h60
  text "X" at 12576.46,3423.12 h60
  text "MATTE" at 12694.46,3423.12 h60
  text "SEMI-GLOSS" at 13312,3422.48 h60
  text "IMMERSION GOLD (ENIG)" at 12394.46,3250.35 h60
  text "ENEPIG" at 13732,3243.13 h60
  text "SURFACE FINISH:" at 11333.46,3242.13 h60
  text "X" at 12216.46,3242.13 h60
  text "IMM. TIN/SILVER OR EQUIV" at 11663,3104.81 h60
  text "OTHER" at 13094.46,3100.87 h60
  text "ARRAY/PANEL:" at 11333.46,2945.5 h60
  text "CUT AND TRIM PER M1 BOARD OUTLINE" at 12394.46,2937.28 h60
  text "N.C. ROUTE" at 12394.46,2801.31 h60
  text "X" at 13082.46,2801.31 h60
  text "V. SCORE" at 13260.46,2801.31 h60
  text "CERTIFICATION:" at 11333.46,2672.18 h60
  text "MATERIALS AND WORKMANSHIP FOR ALL PCBS" at 12058.46,2672.18 h60
  text "TO MEET OR EXCEED THE REQUIREMENTS OF:" at 12058.46,2578.12 h60
  text "X" at 11695.97,2449.49 h60
  text "ANSI IPC-A-600F CLASS ->" at 11823.96,2449.49 h60
  text "X" at 13471.97,2449.49 h60
  text "2" at 13581.96,2449.49 h60
  text "1" at 13266.96,2447.99 h60
  text "3" at 13935.96,2447.99 h60
  text "X" at 12507.97,2301.8 h60
  text "RoHS" at 12635.96,2301.8 h60
  text "OTHER" at 13280.36,2301.8 h60
  text "PER ORDER" at 13677.42,2301.8 h60
  text "ALL BOARDS MUST MEET OR EXCEED UL94-V0 REQUIREMENTS." at 11361,2147.98 h60
  text "PCB MUST BEAR THE UL94V-0 UL REGISTERED MATERIAL ID NUMBER" at 11361,2031.91 h60
  text "ADDITIONAL REQUIREMENTS:" at 11333.46,1862.49 h60
  text "MICROSECTION:" at 11408.23,1755.36 h60
  text "YES" at 12313.96,1755.36 h60
  text "REQUIRED" at 13175.46,1611.03 h60
  text "BARE BOARD ELEC. TEST:" at 11408.23,1608.17 h60
  text "NONE" at 12713.96,1608.17 h60
  text "X" at 13057.46,1608.17 h60
  text "PER ORDER" at 13767.46,1608.17 h60
  text "XX MIL VIAS REQUIRE NON-CONDUCTIVE FILL AND PLANARIZE" at 11576.38,1403.23 h59
  text "XX MIL VIAS REQUIRE CONDUCTIVE FILL AND PLANARIZE" at 11584.38,1299.25 h60
  text "OUTER XX MIL TRACES REQUIRE 50 OHM SINGLE-ENDED IMPEDANCE" at 11583.39,1135.87 h58
  text "LAYER 2 & 3 (INNER LAYERS) XX MIL WIDE, XX MIL SPACE / TRACES REQUIRE 100 OHM DIFFERENTIAL IMPEDANCE" at 11575.39,900.15 h60
  text ".Layer_Name" at 577,-850.08 h60
M11 Gerber Information:
  lines w10: -292,-921.76 6308,-921.76 ; -292,-718.42 6310,-718.42 ; -292,-515.09 -292,-1125.09 3713,-1125.09 6310,-1125.09 6310,-515.09 -291.5,-515.09 -291.5,-1125.09 1284,-1125.09 ; 2173,-1125.09 2173,-515.09 ; 3440,-718.42 3440,-515.09 ; 4280,-718.42 4280,-515.09 ; 4902,-1131.59 4902,-928.76
  text "ALL ARTWORK VIEWED FROM TOP SIDE" at -228.5,-647.26 h60
  text "BOARD #:" at 2248,-647.26 h60
  text ".PRJ_Number" at 2793.5,-647.26 h60
  text "REV:" at 3638,-647.26 h60
  text ".PCB_Rev" at 3929.5,-647.26 h60
  text "SVN REV:" at 4476,-647.26 h60
  text ".VersionControl_RevNumber" at 4982,-647.26 h60
  text "LAYER NAME =" at -228.5,-850.08 h60
  text "TID #:" at 2248,-850.59 h60
  text ".TID" at 2793.5,-850.59 h60
  text "PLOT NAME =" at -228.5,-1055.93 h60
  text ".plot_File_Name" at 577,-1055.93 h60
  text "GENERATED    :" at 2250,-1055.93 h60
  text ".Print_Date" at 3119.5,-1055.93 h60
  text ".Print_Time" at 3848.5,-1055.93 h60
  text "TEXAS INSTRUMENTS" at 5113,-1055.93 h60
M12 Stackup:
  drawing of 191 lines, arcs and shapes, not listed
  text "Layer" at 9811.59,7253.35 h60
  text "Name" at 10221.51,7253.35 h60
  text "Material" at 11151.25,7253.35 h60
  text "Thickness" at 12011.02,7253.35 h60
  text "Constant" at 12660.85,7253.35 h60
  text "Board Layer Stack" at 13230.71,7253.35 h60
  text "1" at 9811.59,7133.35 h60
  text "Top Overlay" at 10221.51,7133.35 h60
  text "2" at 9811.59,7013.35 h60
  text "Top Solder" at 10221.51,7013.35 h60
  text "Solder Resist" at 11151.25,7013.35 h60
  text "0.40mil" at 12011.02,7013.35 h60
  text "3.5" at 12660.85,7013.35 h60
  text "3" at 9811.59,6893.35 h60
  text "Top Layer" at 10221.51,6893.35 h60
  text "Copper" at 11151.25,6893.35 h60
  text "1.40mil" at 12011.02,6893.35 h60
  text "4" at 9811.59,6773.35 h60
  text "Dielectric1" at 10221.51,6773.35 h60
  text "FR-4" at 11151.25,6773.35 h60
  text "59.20mil" at 12011.02,6773.35 h60
  text "4.8" at 12660.85,6773.35 h60
  text "5" at 9811.59,6653.35 h60
  text "Bottom Layer" at 10221.51,6653.35 h60
  text "Copper" at 11151.25,6653.35 h60
  text "1.40mil" at 12011.02,6653.35 h60
  text "6" at 9811.59,6533.35 h60
  text "Bottom Solder" at 10221.51,6533.35 h60
  text "Solder Resist" at 11151.25,6533.35 h60
  text "0.40mil" at 12011.02,6533.35 h60
  text "3.5" at 12660.85,6533.35 h60
  text "7" at 9811.59,6413.35 h60
  text "Bottom Overlay" at 10221.51,6413.35 h60
  text ".Layer_Name" at 577,-850.08 h60
M13 Component Bodies Top:
  text ".Layer_Name" at 577,-850.08 h60
M14 Component Bodies Bottom:
  text ".Layer_Name" at 577,-850.08 h60
M15 Courtyards Top:
  text ".Layer_Name" at 577,-850.08 h60
M16 Courtyards Bottom:
  text ".Layer_Name" at 577,-850.08 h60
Drill Drawing:
  circle w10: c5363.72,3466.69 r27.63
  lines w10: 5336.09,3190.43 5391.34,3190.43 5391.34,3245.68 5336.09,3245.68 5336.09,3190.43 ; 5336.09,3328.56 5349.9,3328.56 5363.72,3314.75 5377.53,3328.56 5391.34,3328.56 5377.53,3342.37 5391.34,3356.19 5377.53,3356.19 5363.72,3370 5349.9,3356.19 5336.09,3356.19 5349.9,3342.37 5336.09,3328.56
  lines w12: 5286,3153.13 8517.49,3153.13 ; 5286,3526.09 8517.49,3526.09 ; 5623.86,3028.81 5623.86,3650.41 ; 5955.86,3028.81 5955.86,3650.41 ; 6592.43,3028.81 6592.43,3650.41 ; 6851.57,3028.81 6851.57,3650.41 ; 7226.72,3028.81 7226.72,3650.41 ; 7951.05,3028.81 7951.05,3650.41 ; 5286,3028.81 8517.49,3028.81 8517.49,3650.41 5286,3650.41 5286,3028.81
  text "Symbol" at 5360.59,3563.39 h72
  text "Quantity" at 5661.16,3563.39 h72
  text "Finished Hole Size" at 5993.16,3563.39 h72
  text "Plated" at 6629.72,3563.39 h72
  text "Hole Type" at 6888.86,3563.39 h72
  text "Drill Layer Pair" at 7264.02,3563.39 h72
  text "Hole Tolerance" at 7988.35,3563.39 h72
  text "172" at 5661.16,3439.07 h60
  text "18.00mil (0.457mm)" at 5993.16,3439.07 h60
  text "PTH" at 6629.72,3439.07 h60
  text "Round" at 6888.86,3439.07 h60
  text "Top Layer - Bottom Layer" at 7264.02,3439.07 h60
  text "18" at 5661.16,3314.75 h60
  text "40.00mil (1.016mm)" at 5993.16,3314.75 h60
  text "PTH" at 6629.72,3314.75 h60
  text "Round" at 6888.86,3314.75 h60
  text "Top Layer - Bottom Layer" at 7264.02,3314.75 h60
  text "10" at 5661.16,3190.43 h60
  text "40.16mil (1.020mm)" at 5993.16,3190.43 h60
  text "PTH" at 6629.72,3190.43 h60
  text "Round" at 6888.86,3190.43 h60
  text "Top Layer - Bottom Layer" at 7264.02,3190.43 h60
  text "200 Total" at 5661.16,3066.11 h60
  text ".Layer_Name" at 577,-850.08 h60
M17 Embedded Cavity:
  text ".Layer_Name" at 577,-850.08 h60
M18 Embedded Assembly:
  text ".Layer_Name" at 577,-850.08 h60
M19 Embedded Keepout:
  text ".Layer_Name" at 577,-850.08 h60

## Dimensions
0,0 to 0,2000 on M2 Board Dimensions
0,-391.59 to 1000,-391.59 on M2 Board Dimensions
0,8.41 to 5413.39,0 on M2 Board Dimensions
